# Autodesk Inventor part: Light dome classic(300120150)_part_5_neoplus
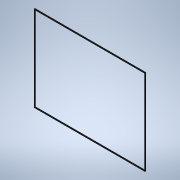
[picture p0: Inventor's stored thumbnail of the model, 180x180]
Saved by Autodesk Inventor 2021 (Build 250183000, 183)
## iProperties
Created: 2026-04
Part Number: Light dome classic(300120150)_part_5_neoplus
Material: Generic
Catalog Web Link: www.3dfindit.com
Description: Light dome classic_part_5_neoplus-
Vendor: KINGSPAN
Document SubType Name: Modeling
Designer: psAdmin
Manufacturer: KINGSPAN
Mass: 534.126 g
Surface Area: 2004.36 cm^2
Volume: 534.126 cm^3
Density: 1 g/cm^3
Appearance: PSOLRGB-128-128-128
Category: PARTsolutions
Company: KINGSPAN
Title: Light dome classic(300120150)_part_5_neoplus
Author: Cadenas PARTsolutions
PSOL_IDENT_0: {$CADENAS_DATA/23d-libs/kingspan_kla/light_dome_classic_neoplus/parts/part_5.prj},268 {VTYP=3D},{NB=
PSOL_IDENT_1: Light dome classic(300120150)_part_5_neoplus},{LINA=Light dome classic(300120150)_part_5_neoplus},{N
PSOL_IDENT_2: N=Light dome classic_part_5_neoplus},{DATE=20.03.2025 09:30:52},{GEOMDATE=21.11.2022 13:10:00},{VERS
PSOL_IDENT_3: ION=},{LINEID=10},{WBVAR=LODLEVEL,L,W},{WBNUMERIC=W}  {NB=Light dome classic(300120150)_part_5_neopl
PSOL_IDENT_4: us},{LINA=Light dome classic(300120150)_part_5_neoplus},{KT=DUMMY},{IDNR=},{PN=Light dome classic},{
PSOL_IDENT_5: LODLEVEL=300},{L=120},{W=150},{WX=120,150,180,240,270,300},{LX=1200},{XWX=1500}
NB: Light dome classic(300120150)_part_5_neoplus
NN: Light dome classic_part_5_neoplus
NBSYN: $PN.($LODLEVEL.$L.$W.)_part_5_neoplus
LINA: Light dome classic(300120150)_part_5_neoplus
CATALOG: Light + Air
PN: Light dome classic
LODLEVEL: 300
L: 120
W: 150
SUPPLIER: KINGSPAN
ARTICLENO: Light dome classic(300120150)_part_5_neoplus
BOMINFO: Light dome classic(300120150)_part_5_neoplus
CREATOR: CADENAS GmbH
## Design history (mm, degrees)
sketch "Sketch_1"
  geometry: L1 (-645.21, 12.944)-(-645.21, 25.446); L2 (-645.21, 25.446)-(-654.5, 25.446); L3 (-654.5, 25.446)-(-654.5, 12.944); L4 (-654.5, 12.944)-(-645.21, 12.944)
  constraints: 8 end point
extrude "Extrusion1" join sketch "Sketch_1" stored distance "d0" = 2400; taper "d1" = 0 deg
sketch "Sketch_2"
  geometry: L1 (504.5, 25.446)-(495.21, 25.446); L2 (495.21, 25.446)-(495.21, 12.944); L3 (495.21, 12.944)-(504.5, 12.944); L4 (504.5, 12.944)-(504.5, 25.446)
  constraints: 8 end point
extrude "Extrusion2" join sketch "Sketch_2" stored distance "d2" = 3000; taper "d3" = 0 deg
sketch "Sketch_3"
  geometry: L1 (654.5, 12.944)-(654.5, 25.446); L2 (654.5, 25.446)-(645.21, 25.446); L3 (645.21, 25.446)-(645.21, 12.944); L4 (645.21, 12.944)-(654.5, 12.944)
  constraints: 8 end point
extrude "Extrusion3" join sketch "Sketch_3" stored distance "d4" = 2400; taper "d5" = 0 deg
sketch "Sketch_4"
  geometry: L1 (-504.5, 25.446)-(-504.5, 12.944); L2 (-504.5, 12.944)-(-495.21, 12.944); L3 (-495.21, 12.944)-(-495.21, 25.446); L4 (-495.21, 25.446)-(-504.5, 25.446)
  constraints: 8 end point
extrude "Extrusion4" join sketch "Sketch_4" stored distance "d6" = 3000; taper "d7" = 0 deg
sketch "Sketch_5"
  geometry: L1 (-654.5, 3.096)-(-654.5, 25.446); L2 (-654.5, 25.446)-(-2146.516, 25.446); L3 (-2146.516, 25.446)-(-2146.516, 3.096); L4 (-2146.516, 3.096)-(-654.5, 3.096)
  constraints: 8 end point
extrude "Extrusion5" cut sketch "Sketch_5" stored distance "d8" = 3000; taper "d9" = 0 deg
sketch "Sketch_6"
  geometry: L1 (1996.516, 25.446)-(504.5, 25.446); L2 (504.5, 25.446)-(504.5, 3.096); L3 (504.5, 3.096)-(1996.516, 3.096); L4 (1996.516, 3.096)-(1996.516, 25.446)
  constraints: 8 end point
extrude "Extrusion6" cut sketch "Sketch_6" stored distance "d10" = 3000; taper "d11" = 0 deg
sketch "Sketch_7"
  geometry: L1 (2146.516, 25.446)-(654.5, 25.446); L2 (654.5, 25.446)-(654.5, 3.096); L3 (654.5, 3.096)-(2146.516, 3.096); L4 (2146.516, 3.096)-(2146.516, 25.446)
  constraints: 8 end point
extrude "Extrusion7" cut sketch "Sketch_7" stored distance "d12" = 3000; taper "d13" = 0 deg
sketch "Sketch_8"
  geometry: L1 (-1996.516, 25.446)-(-1996.516, 3.096); L2 (-1996.516, 3.096)-(-504.5, 3.096); L3 (-504.5, 3.096)-(-504.5, 25.446); L4 (-504.5, 25.446)-(-1996.516, 25.446)
  constraints: 8 end point
extrude "Extrusion8" cut sketch "Sketch_8" stored distance "d14" = 3000; taper "d15" = 0 deg
node "IP_5_XY"
node "IP_5_YZ"
node "IP_5_ZX"
node "IP_5_X"
node "IP_5_Y"
node "IP_5_Z"
node "IP_5_Center"
body "Solid1"
other parameters: "d16" = 0
